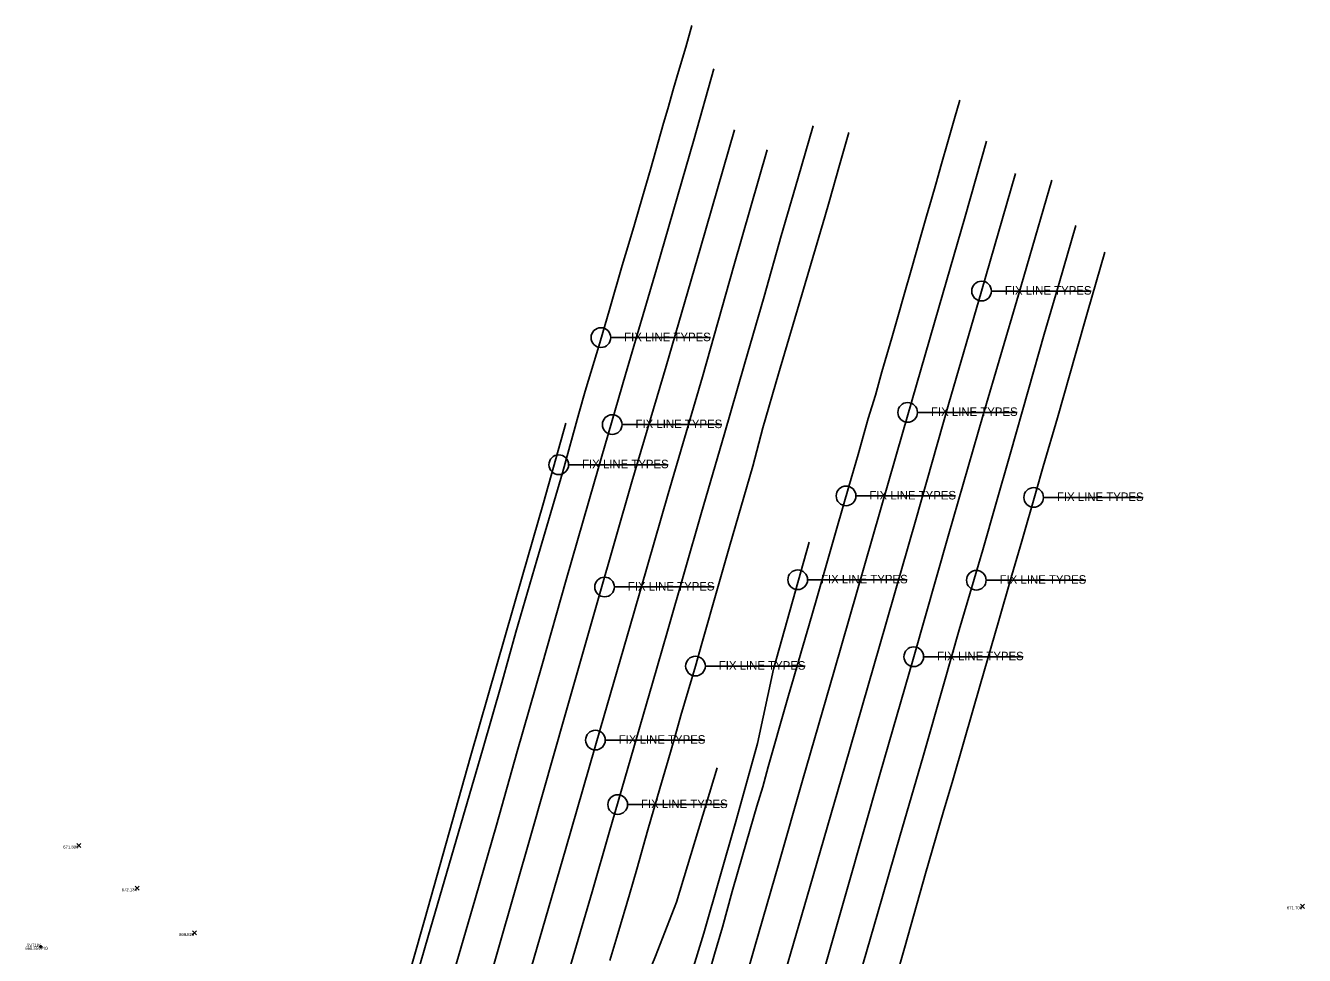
# Model space of a CAD drawing. Extents: x 1659932 to 1663108, y 619867 to 620611.
# Drawn here: x 1661187.9 to 1661608.8, y 620305.2 to 620611.2 of the extents above; entities that cross this region are included whole.
import ezdxf

# ---------------------------------------------------------------- set-up
doc = ezdxf.new("R2010")
doc.units = 0
for name, color, linetype in [('DR_X_Elev_Flow', 7, 'Continuous'), ('PM_X_Edge_Line', 7, 'Continuous'), ('PM_X_Lane_Line', 7, 'Continuous'), ('PV_X_EOP', 7, 'Continuous'), ('RD_X_Fence', 7, 'Continuous'), ('RD_X_GR_Lt', 7, 'Continuous'), ('RD_X_GR_Rt', 7, 'Continuous'), ('SC_Scratch6', 7, 'Continuous'), ('SV_X_Random_Point', 7, 'Continuous'), ('SV_X_Text_Comment', 7, 'Continuous'), ('SV_X_Text_Elevation', 7, 'Continuous'), ('SV_X_Text_Name', 7, 'Continuous')]:
    doc.layers.add(name, color=color, linetype=linetype)

msp = doc.modelspace()

# ---------------------------------------------------------------- linework, layer by layer
at = {"layer": 'DR_X_Elev_Flow'}
for p, q in [((1661192.42, 620307.99), (1661193.42, 620307.99)), ((1661192.92, 620308.49), (1661192.92, 620307.49)), ((1661192.92, 620307.99), (1661192.92, 620307.99))]:
    msp.add_line(p, q, dxfattribs=at)
at = {"layer": 'PM_X_Edge_Line'}
for points in [[(1661314.92, 620250.98), (1661320.24, 620269.45), (1661324.21, 620283.38), (1661329.68, 620302.28), (1661336.02, 620324.07), (1661342.92, 620348.04), (1661349.76, 620372.22), (1661357.79, 620400.47), (1661365.87, 620428.74), (1661375.17, 620461.08), (1661385.4, 620496.29), (1661395.58, 620531), (1661407.96, 620573.95), (1661414.41, 620596.94)], [(1661447.15, 620578.18), (1661442.08, 620560.71), (1661436.66, 620541.93), (1661430.96, 620522.04), (1661424.5, 620499.71), (1661417.8, 620476.46), (1661410.39, 620450.9), (1661399.15, 620411.88), (1661394.24, 620394.79), (1661380.03, 620345.6), (1661374.37, 620326.1), (1661366.48, 620299.21), (1661362.47, 620285.11), (1661357.43, 620267.56), (1661352.49, 620250.24)], [(1661533.64, 620545.42), (1661528.11, 620526.36), (1661523.21, 620509.62), (1661518.01, 620491.43), (1661511.99, 620470.17), (1661507.32, 620453.72), (1661503, 620438.64), (1661498.7, 620424.14), (1661495.25, 620412.32), (1661490.2, 620394.57), (1661483.24, 620370.32), (1661475.77, 620344.72), (1661468.35, 620318.81), (1661463.7, 620302.95), (1661458.9, 620285.65), (1661453.93, 620268.51), (1661449.63, 620253.6), (1661448.09, 620248.46)], [(1661411.11, 620249.28), (1661421.23, 620284.65), (1661427.96, 620308.09), (1661435.85, 620335.4), (1661443.68, 620362.67)]]:
    msp.add_lwpolyline(points, dxfattribs=at)
at = {"layer": 'PM_X_Lane_Line'}
for points in [[(1661332.33, 620268.36), (1661343.26, 620306.38), (1661354.65, 620346.19), (1661365.24, 620383.52), (1661376.49, 620422.77), (1661387.47, 620460.99), (1661398.71, 620499.13), (1661410.08, 620538.06), (1661421.21, 620576.86)], [(1661431.96, 620570.3), (1661421.04, 620532.1), (1661410.7, 620495.6), (1661399.42, 620457.06), (1661388.16, 620417.77), (1661377.14, 620379.94), (1661365.7, 620340.36), (1661354.27, 620301.08), (1661343.5, 620263.55)], [(1661443.68, 620362.67), (1661454.12, 620399.17), (1661476.65, 620477.4), (1661488.55, 620518.38), (1661497.14, 620548.39), (1661504.23, 620573.1)], [(1661424.05, 620251.26), (1661435.15, 620290.2), (1661446.11, 620327.94), (1661457.55, 620367.38), (1661469.01, 620406.96), (1661480.91, 620448.46), (1661491.72, 620486.44), (1661502.57, 620523.8), (1661513.73, 620562.48)], [(1661525.68, 620560.35), (1661514.72, 620522.51), (1661503.09, 620483.06), (1661491.6, 620443.16), (1661480.26, 620403.46), (1661469.09, 620364.67), (1661458.33, 620327), (1661447.31, 620288.52), (1661436.53, 620250.63)]]:
    msp.add_lwpolyline(points, dxfattribs=at)
at = {"layer": 'PV_X_EOP'}
for points in [[(1661316.46, 620297.78), (1661320.54, 620311.85), (1661332.62, 620353.2), (1661338.26, 620372.72), (1661344.62, 620394.89), (1661349.31, 620411.52), (1661356.17, 620435.19), (1661364.6, 620464.02), (1661370.04, 620483.55), (1661372.1, 620490.81), (1661376.94, 620506.8), (1661380.21, 620518.1), (1661384.31, 620532.22), (1661386.46, 620539.48), (1661388.3, 620545.68), (1661390.96, 620554.84), (1661393.56, 620563.83), (1661397.91, 620579.09), (1661399.28, 620583.75), (1661401.2, 620590.5), (1661402.85, 620596.07), (1661405.18, 620604.06), (1661407.23, 620611.17)], [(1661495.46, 620586.65), (1661493.69, 620580.6), (1661491.52, 620572.86), (1661489.42, 620565.71), (1661487.49, 620559.02), (1661486.04, 620554.08), (1661484.43, 620548.5), (1661482.48, 620541.56), (1661479.39, 620530.66), (1661477.14, 620522.67), (1661475.02, 620515.31), (1661473.02, 620508.43), (1661469.7, 620497.23), (1661467.61, 620489.53), (1661465.29, 620481.84), (1661461.96, 620470), (1661458.87, 620459.48), (1661454.93, 620445.8), (1661452.07, 620435.76), (1661450.31, 620429.59), (1661448.33, 620422.72), (1661445.72, 620413.65), (1661443.32, 620405.43), (1661440.68, 620396.24), (1661439.01, 620390.7), (1661436.4, 620381.43), (1661434.36, 620374.17), (1661432.38, 620367.2), (1661430.54, 620360.68), (1661428.65, 620354.26), (1661423.99, 620338.35), (1661420.53, 620326.14), (1661417.32, 620314.43), (1661414.66, 620305.55), (1661411.67, 620295.13)], [(1661458.88, 620575.95), (1661455.83, 620565.26), (1661452.41, 620553.18), (1661450.96, 620548.18), (1661443.97, 620524.48), (1661435.69, 620496.55), (1661430.55, 620478.76), (1661427.28, 620466.13), (1661419.57, 620439.72), (1661415.83, 620426.7), (1661410.47, 620407.83), (1661408.41, 620400.37), (1661403.61, 620384.1), (1661401.64, 620376.97), (1661399.38, 620369.46), (1661396.71, 620360.09), (1661392.76, 620346.44), (1661389.05, 620333.5), (1661386.69, 620325.18), (1661382.86, 620312.25), (1661380.23, 620303.47)], [(1661460.21, 620248.19), (1661465.73, 620267.26), (1661477.47, 620308.26), (1661484.14, 620332.15), (1661489.98, 620352.15), (1661493.17, 620362.87), (1661496.77, 620375.46), (1661502.25, 620394.51), (1661508.04, 620414.59), (1661512.58, 620430.25), (1661515.8, 620441.46), (1661520.55, 620457.99), (1661522.89, 620466.1), (1661527.54, 620482.08), (1661533.62, 620503.39), (1661537.44, 620516.81), (1661543.13, 620536.58)]]:
    msp.add_lwpolyline(points, dxfattribs=at)
at = {"layer": 'RD_X_Fence'}
msp.add_lwpolyline([(1661392.7, 620249.89), (1661399.55, 620274.75), (1661406.93, 620298.58), (1661411.13, 620312.51), (1661421.74, 620349.21), (1661428.86, 620374.88), (1661434.08, 620399.32), (1661445.83, 620441.2)], dxfattribs=at)
at = {"layer": 'RD_X_GR_Lt'}
msp.add_lwpolyline([(1661415.5, 620366.85), (1661402.13, 620322.68), (1661395.2, 620304.89), (1661390.45, 620293.01), (1661382.74, 620273.5), (1661377.01, 620255.73)], dxfattribs=at)
at = {"layer": 'RD_X_GR_Rt'}
msp.add_lwpolyline([(1661365.74, 620480.35), (1661358.38, 620454.11), (1661351.31, 620429.73), (1661342.87, 620400.4), (1661334.47, 620370.93), (1661319.26, 620316.75), (1661307.3, 620274.78)], dxfattribs=at)
at = {"layer": 'SC_Scratch6'}
for p, q in [((1661505.81, 620523.8), (1661538.61, 620523.8)), ((1661380.51, 620508.48), (1661413.31, 620508.48)), ((1661481.5, 620483.87), (1661514.3, 620483.87)), ((1661384.25, 620479.87), (1661417.05, 620479.87)), ((1661366.64, 620466.66), (1661399.44, 620466.66)), ((1661461.22, 620456.39), (1661494.02, 620456.39)), ((1661522.96, 620455.87), (1661555.77, 620455.87)), ((1661445.3, 620428.78), (1661478.1, 620428.78)), ((1661504.09, 620428.65), (1661536.89, 620428.65)), ((1661381.72, 620426.41), (1661414.52, 620426.41)), ((1661483.51, 620403.46), (1661516.31, 620403.46)), ((1661411.66, 620400.37), (1661444.46, 620400.37)), ((1661378.72, 620376.01), (1661411.53, 620376.01)), ((1661386.04, 620354.82), (1661418.84, 620354.82))]:
    msp.add_line(p, q, dxfattribs=at)
for centre in [(1661502.57, 620523.8), (1661377.26, 620508.48), (1661478.25, 620483.87), (1661381, 620479.87), (1661363.4, 620466.66), (1661457.97, 620456.39), (1661519.72, 620455.87), (1661442.05, 620428.78), (1661500.85, 620428.65), (1661378.47, 620426.41), (1661480.26, 620403.46), (1661408.41, 620400.37), (1661375.48, 620376.01), (1661382.8, 620354.82)]:
    msp.add_circle(centre, 3.24, dxfattribs=at)
at = {"layer": 'SV_X_Random_Point'}
for p, q in [((1661204.73, 620340.65), (1661206.07, 620341.99)), ((1661204.73, 620341.99), (1661206.07, 620340.65)), ((1661223.98, 620326.62), (1661225.31, 620327.95)), ((1661223.98, 620327.95), (1661225.31, 620326.62)), ((1661607.51, 620320.65), (1661608.84, 620321.99)), ((1661607.51, 620321.99), (1661608.84, 620320.65)), ((1661242.87, 620311.9), (1661244.2, 620313.23)), ((1661242.87, 620313.23), (1661244.2, 620311.9))]:
    msp.add_line(p, q, dxfattribs=at)

# ---------------------------------------------------------------- texts
at = {"layer": 'SC_Scratch6'}
for p in [(1661510.24, 620522.64), (1661384.93, 620507.31), (1661485.93, 620482.7), (1661388.68, 620478.7), (1661371.07, 620465.49), (1661465.65, 620455.22), (1661527.39, 620454.71), (1661386.14, 620425.25), (1661449.73, 620427.61), (1661508.52, 620427.49), (1661416.09, 620399.2), (1661487.93, 620402.3), (1661383.15, 620374.84), (1661390.47, 620353.65)]:
    msp.add_text('FIX LINE TYPES', height=2.8, dxfattribs=at).set_placement(p)
at = {"layer": 'SV_X_Text_Comment'}
msp.add_text('PIO', height=1, dxfattribs=at).set_placement((1661192.92, 620306.99))
at = {"layer": 'SV_X_Text_Elevation'}
for s, p in [('671.896', (1661200.3, 620340.32)), ('672.134', (1661219.52, 620326.29)), ('671.708', (1661603.08, 620320.32)), ('668.820', (1661238.42, 620311.56)), ('668.559', (1661187.83, 620306.99))]:
    msp.add_text(s, height=1, dxfattribs=at).set_placement(p)
at = {"layer": 'SV_X_Text_Name'}
msp.add_text('SV7186', height=1, dxfattribs=at).set_placement((1661188.21, 620307.99))

doc.saveas('drawing.dxf')
